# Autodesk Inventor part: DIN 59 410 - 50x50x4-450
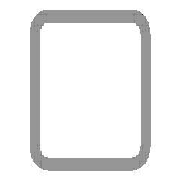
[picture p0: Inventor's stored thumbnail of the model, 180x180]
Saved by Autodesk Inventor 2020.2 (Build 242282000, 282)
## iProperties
Manager: www.cadconsulting.pl
Company: Fabian Stasiak CAD Consulting
Created: 2015-01
Part Number: DIN 59 410 - 50x50x4-450
Material: Stal, miękka
Description: Rurki stalowe o przekroju kwadratowym formowane na gorąco
Document SubType Name: Modellieren
Standard: DIN
Designer: F.Stasiak
Standards Organization: DIN
Language: pl-PL
Size Designation: 50x50x4
Categories: <MemberInstance><Categories><Category DisplayName="Kształtowniki konstrukcyjne" InternalName="089c4875-fa83-4c05-b084-43b9cc11f5ed" Mnemonic="GRDR"><CategoryPar
Stock Number: 50x50x4
Density: 7.85 g/cm^3
Appearance: Częściowo polerowana
Mass: 2508.91 g
Surface Area: 1611.93 cm^2
Volume: 319.606 cm^3
Catalog Web Link: www.expertbooks.pl
_CCFamilyMember: 40
_CCFamilyDisplayName: DIN 59410 (Kwadrat) - Rurki stalowe o przekroju kwadratowym formowane na gorąco
_FrameMemberDoc: Frame Member File
_Version: 15.0.0
_GetPNFromCC: 1
G_W: 50,000 mm
G_H: 50,000 mm
G_L: 450,000 mm
+6234DFDA-CA16-4E29-9939-9BE6E3237671+CUTDETAIL3: Wytnij
+2734601A-B7E4-453D-A6C9-8EA31CAAE1E7+CUTDETAIL4: Wytnij
IsCustomPart: 1
Author: F.Stasiak
Subject: Zbiór ćwiczeń. Autodesk Inventor 2020. Kurs Professional
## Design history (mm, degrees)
node "Płaszczyzna początkowa"
node "Płaszczyzna końcowa"
sketch "Szkic"
  geometry: L1 (-17, 25)-(17, 25); L2 (25, 17)-(25, -17); L3 (17, -25)-(-17, -25); L4 (-25, -17)-(-25, 17); L5 (-37.32, 0)-(37.32, 0) reference; L6 (0, -37.32)-(0, 37.32) reference; L7 (-17, 21)-(17, 21); L8 (21, 17)-(21, -17); L9 (17, -21)-(-17, -21); L10 (-21, -17)-(-21, 17); A1 r 8 centre (-17, 17) between (-17, 25) and (-25, 17); A2 r 8 centre (17, 17) between (25, 17) and (17, 25); A3 r 8 centre (17, -17) between (17, -25) and (25, -17); A4 r 8 centre (-17, -17) between (-25, -17) and (-17, -25); A5 r 4 centre (-17, 17) between (-17, 21) and (-21, 17); A6 r 4 centre (17, 17) between (21, 17) and (17, 21); A7 r 4 centre (17, -17) between (17, -21) and (21, -17); A8 r 4 centre (-17, -17) between (-21, -17) and (-17, -21); 3 further points
  constraints: 16 end point, 16 point on circle, 8 centre point, 8 tangent, 6 point on line, 4 parallel, 3 equal radius, 3 perpendicular, 1 horizontal, 7 other
  dimensions: "b" = 50 distance of point (-25, 25) point (25, 25); "msp_r" = 8 radius of A1 (= 2 x ParT); "d8" = 25 distance between parallel lines of L4 L6 (= d9); "d9" = 25 distance between parallel lines of L3 L5 (= 0.5 x b); "d10" = 4 distance between parallel lines of L3 L9 (= ParT)
extrude "Bryła" new body sketch "Szkic" taper "d4" = 0 deg; stored distance "NLG" = 10
node "Driven Length"
  sketch "Sketch2"
    geometry: L1 (0, 0)-(10, 0) reference
    constraints: 2 end point, 1 horizontal
  workplane "Work Plane3"
  sketch "Sketch3"
    geometry: L1 (-2, 25)-(12, 25) reference; L2 (-2, 475)-(12, 475) reference
    dimensions: "d14" = 450 distance between parallel lines of L1 L2 (derived)
node "Płaszczyzna konstrukcyjna6"
feature "Podział3"
node "Płaszczyzna konstrukcyjna7"
feature "Podział4"
body "Solid1"
other parameters: "ParT" = 4, "G_OFFSET_START" = -25 [user parameter; used in 1 equation term], "G_OFFSET_END" = 25 [user parameter; used in 1 equation term], "d11" = 25 (= -G_OFFSET_START), "d12" = 475 (= G_OFFSET_END + B_L), "G_L" = 450 (= d14) [user parameter], "d13" = 90 deg
